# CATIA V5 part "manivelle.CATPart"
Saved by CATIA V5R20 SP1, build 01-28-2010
Part number: manivelle
Bounding box of the stored display mesh (mm): x -148 to 25, y -165 to 65, z -335 to -105
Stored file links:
  C:\Users\Fabien-port\Desktop\test\manivelle.CATPart
  C:\Users\Fabien-port\Desktop\test\mecanisme_a_coulisseau.CATProduct
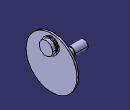
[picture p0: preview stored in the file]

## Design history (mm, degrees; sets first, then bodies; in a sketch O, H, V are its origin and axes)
External parameters (linked from other documents)
  External.entraxe_manivelle = 70 mm
  External.cote_coulisseau = 30 mm
  External.epaisseur_bielle = 8 mm
  External.largeur_bielle = 15 mm
  External.rayon_cylindre_bielle = 10 mm
  External.grand_rayon_bielle5 = 50 mm
Set1
  Plane1 "Plan_pivot_A": linked copy from another document
  Point1 "PointA": linked copy from another document
  Point2 "Point_entraxe": linked copy from another document
Body1 (main body)
  Sketch1 on Plane1, origin (0, 0, 0), H (0, 1, 0), V (0, 0, 1)
    point P1 (-50, -220)
    circle A1 centre (-50, -220) radius 115
    point P2 (-50, -220)
    reference projected point E1 (-50, -220) from Point1
    radius A1 = 115 {= External.entraxe_manivelle +External.grand_rayon_bielle5/2 +20mm}
    coincidence: P2 E1
  Pad1: profile Sketch1, direction (-1, 0, 0), length 8 {= External.epaisseur_bielle}
  Sketch2 on end face of Pad1, origin (-8, 0, 0), H (0, -1, 0), V (0, 0, 1)
    circle A1 centre (50, -220) radius 20
    point P1 (50, -220)
    reference projected point E1 (50, -220) from Point1
    distance P1 E1 = 0
    radius A1 = 20 {= External.rayon_cylindre_bielle *2.0}
  Pad2: profile Sketch2, direction (-1, 0, 0), length 1
  Sketch3 on end face of Pad2, origin (-9, 0, 0), H (0, -1, 0), V (0, 0, 1)
    circle A1 centre (50, -220) radius 18
    point P1 (50, -220)
    reference projected point E1 (50, -220) from Point1
    distance P1 E1 = 0
    radius A1 = 18 {= External.rayon_cylindre_bielle *1.8}
  Pad3: profile Sketch3, direction (-1, 0, 0), length 78 {= External.epaisseur_bielle *6+External.cote_coulisseau}
  Sketch4 on end face of Pad3, origin (-87, 0, 0), H (0, -1, 0), V (0, 0, 1)
    circle A1 centre (50, -220) radius 20
    point P1 (50, -220)
    reference projected point E1 (50, -220) from Point1
    radius A1 = 20 {= External.rayon_cylindre_bielle *2.0}
    distance P1 E1 = 0
  Pad4: profile Sketch4, direction (-1, 0, 0), length 1
  Sketch5 on start face of Pad1, origin (0, 0, 0), H (0, 1, 0), V (0, 0, 1)
    circle A1 centre (-50, -150) radius 35
    point P1 (-50, -150)
    reference projected point E1 (-50, -150) from Point2
    distance P1 E1 = 0
    radius A1 = 35 {= 3/5*External.grand_rayon_bielle5 +5mm}
  Pad5: profile Sketch5, direction (1, 0, 0), length 1
  Sketch6 on end face of Pad5, origin (1, 0, 0), H (0, 1, 0), V (0, 0, 1)
    circle A1 centre (-50, -150) radius 30
    point P1 (-50, -150)
    reference projected point E1 (-50, -150) from Point2
    distance P1 E1 = 0
    radius A1 = 30 {= 3/5*External.grand_rayon_bielle5}
  Pad6: profile Sketch6, direction (1, 0, 0), length 8 {= External.epaisseur_bielle}
  Sketch7 on end face of Pad6, origin (9, 0, 0), H (0, 1, 0), V (0, 0, 1)
    circle A1 centre (-50, -150) radius 35
    point P1 (-50, -150)
    reference projected point E1 (-50, -150) from Point2
    distance P1 E1 = 0
    radius A1 = 35 {= 3/5*External.grand_rayon_bielle5 +5mm}
  Pad7: profile Sketch7, direction (1, 0, 0), length 1
  Sketch8 on end face of Pad4, origin (-88, 0, 0), H (0, -1, 0), V (0, 0, 1)
    circle A1 centre (50, -220) radius 18
    point P1 (50, -220)
    reference projected point E1 (50, -220) from Point1
    distance P1 E1 = 0
    radius A1 = 18 {= 1.8*External.rayon_cylindre_bielle}
  Pad8: profile Sketch8, direction (-1, 0, 0), length 60
  Sketch9 on end face of Pad7, origin (10, 0, 0), H (0, 1, 0), V (0, 0, 1)
    circle A1 centre (-50, -150) radius 30
    point P1 (-50, -150)
    reference projected point E1 (-50, -150) from Point2
    distance P1 E1 = 0
    radius A1 = 30 {= 3/5*External.grand_rayon_bielle5}
  Pad9: profile Sketch9, direction (1, 0, 0), length 15
Relations
  Pad4.FirstLimit.Length = External.rayon_cylindre_bielle *2.7 (deactivated)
